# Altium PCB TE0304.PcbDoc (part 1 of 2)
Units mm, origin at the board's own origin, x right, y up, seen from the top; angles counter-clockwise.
Board outline 115 x 73 mm, 4 copper layers (L 01 (Top), L 02, L 03, L 04 (Bot)), stack 1.564 mm thick; 95 components, 174 nets, 553 pads, 126 vias.
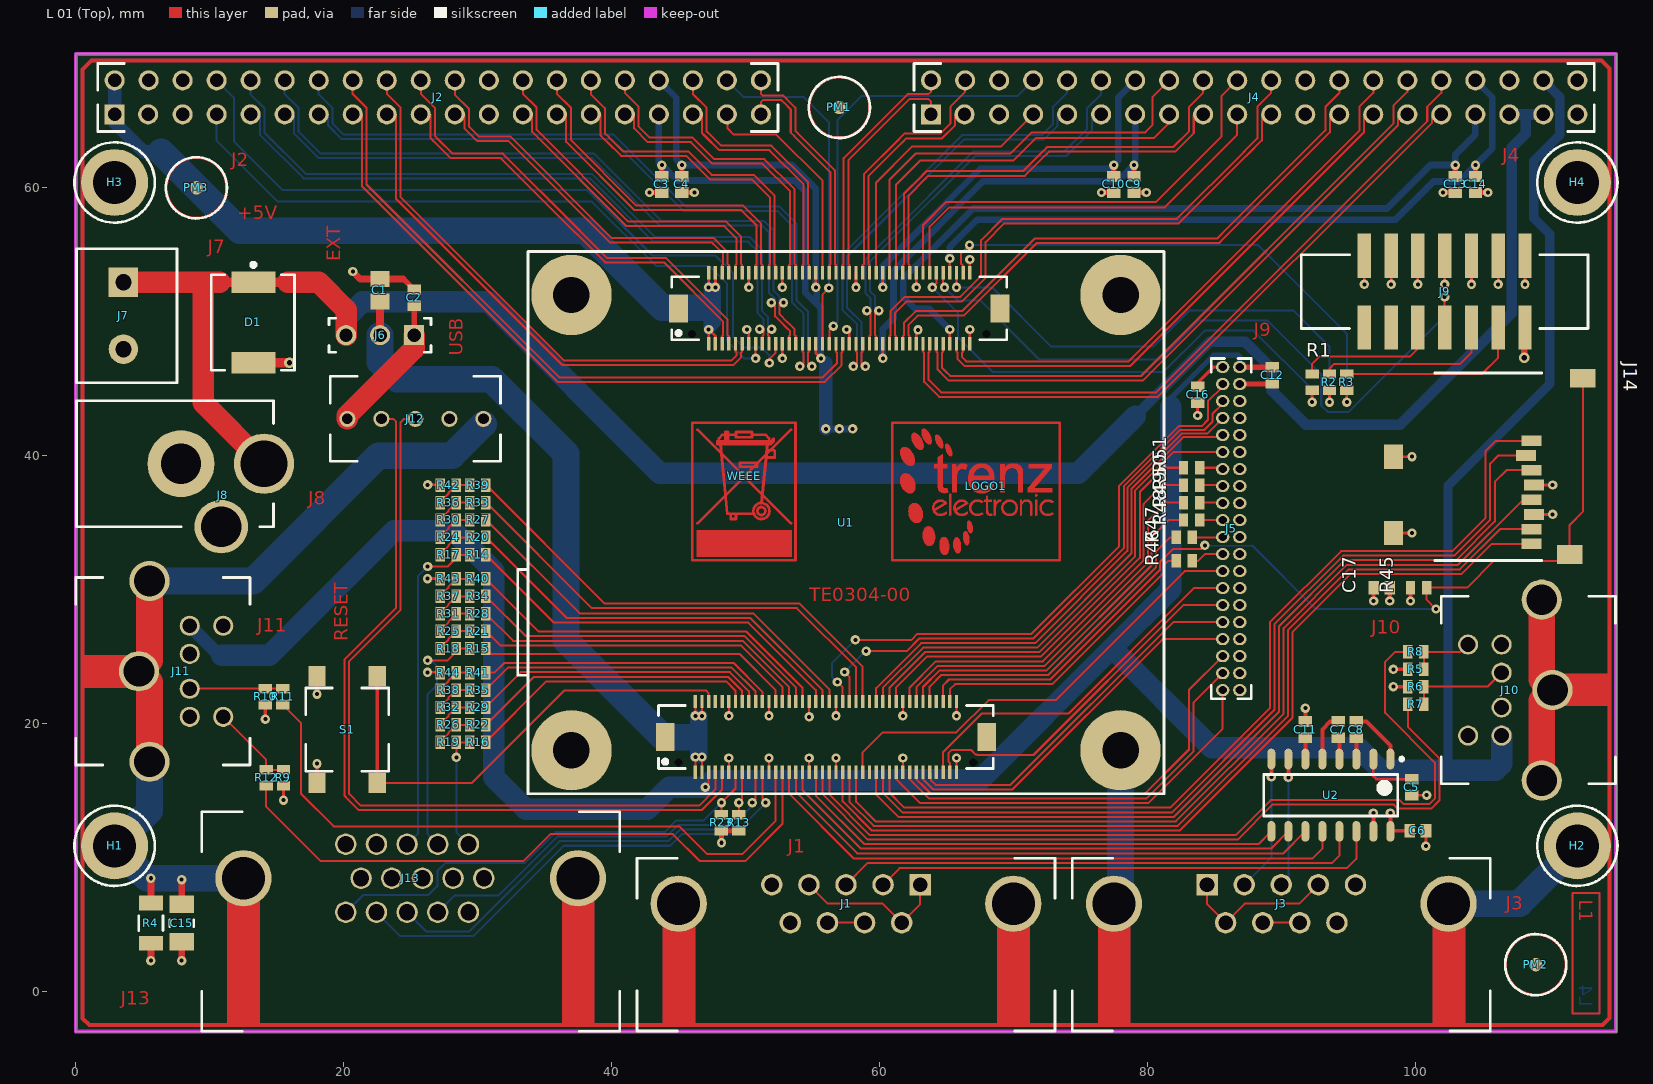
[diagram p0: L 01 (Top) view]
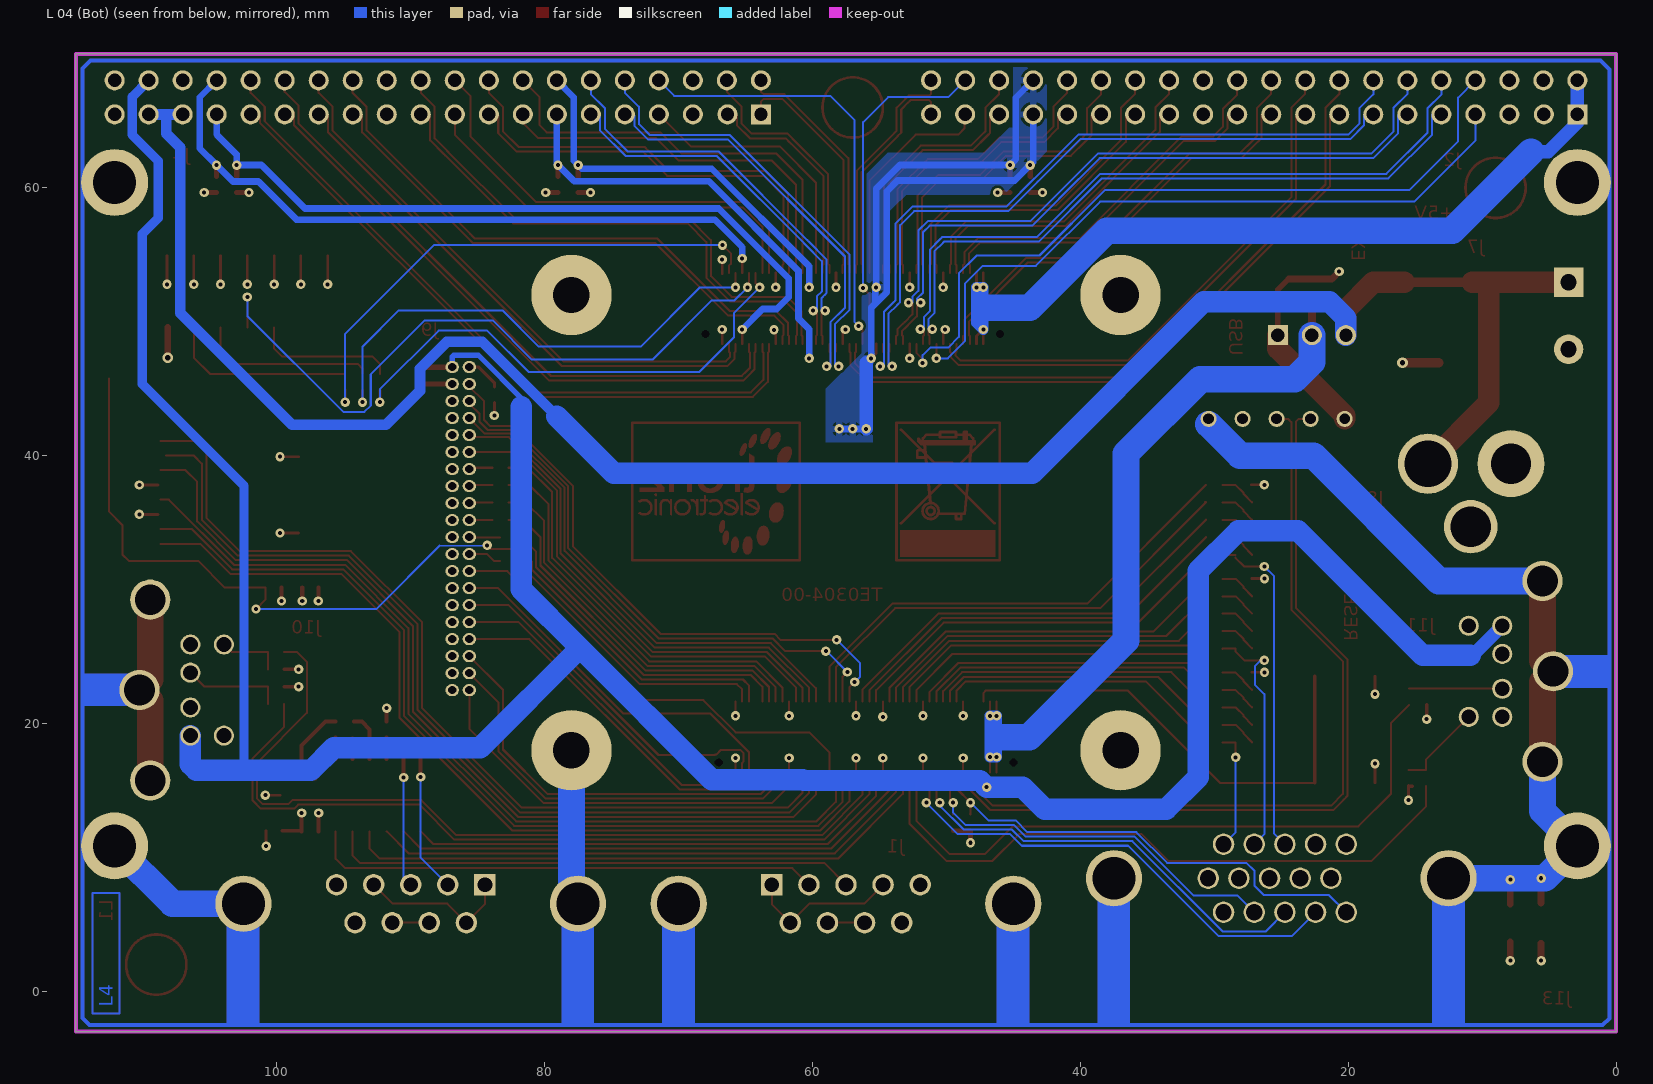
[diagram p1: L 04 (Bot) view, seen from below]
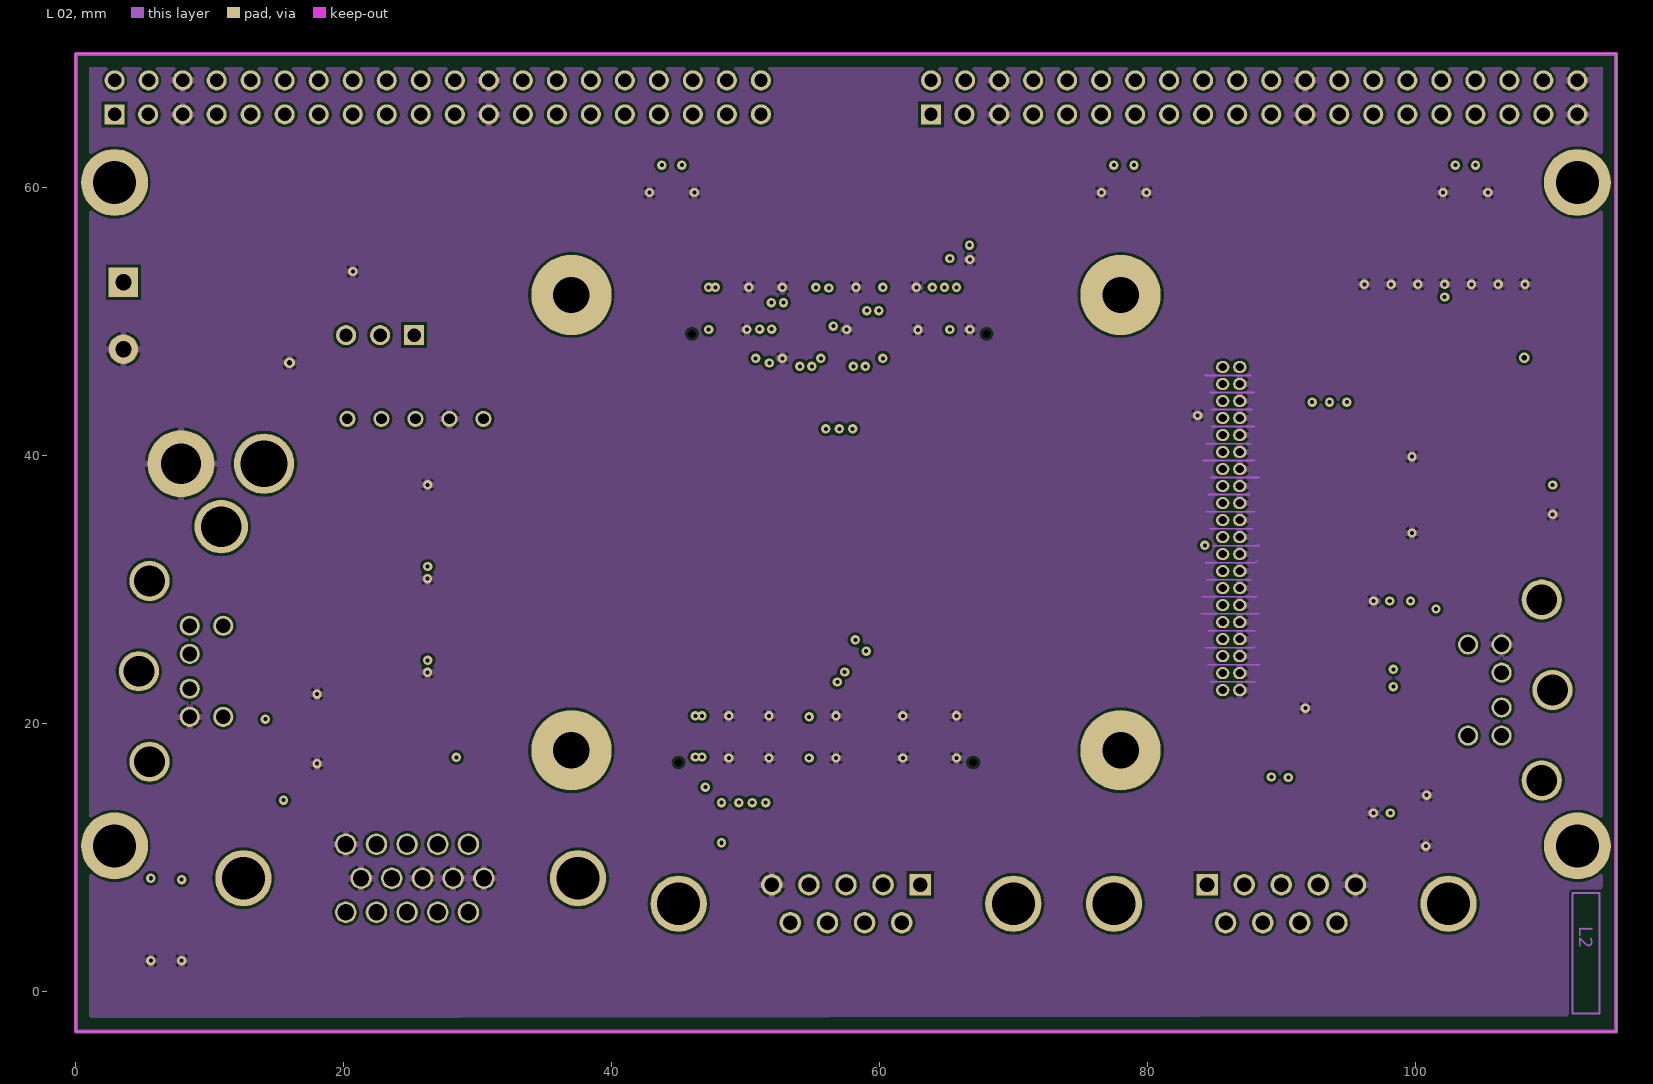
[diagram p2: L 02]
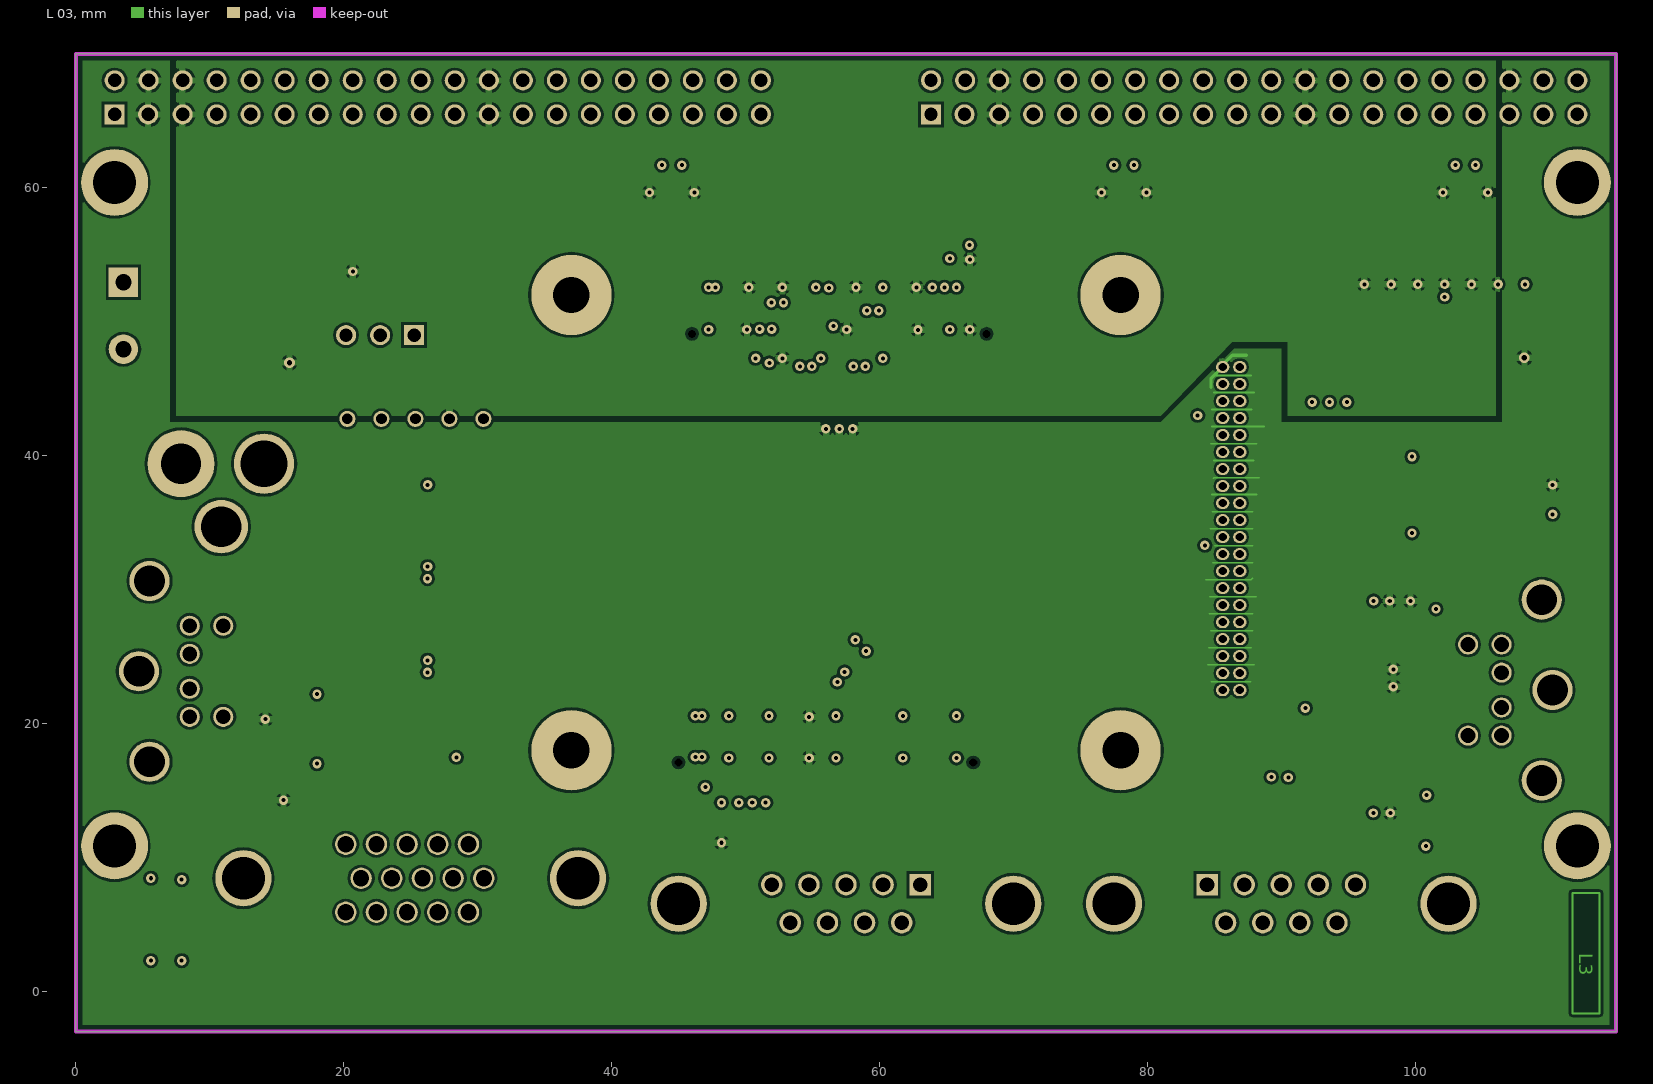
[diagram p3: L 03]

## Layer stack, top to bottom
L 01 (Top): signal copper 0.05
Dielectric: core 0.134, FR-4, Dk 4.8
L 02: signal copper 0.033
Dielectric: prepreg 1.13, FR-4, Dk 4.8
L 03: signal copper 0.033
Dielectric: core 0.134, FR-4, Dk 4.8
L 04 (Bot): signal copper 0.05

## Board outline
0,-3 0,70 115,70 115,-3

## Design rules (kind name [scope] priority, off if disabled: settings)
Clearance Clearance_Polygon [(InPolygon)] p1: gap=0.2
Clearance [All] p2: gap=0.12
ComponentClearance ComponentClearance_WEEE [(InComponent('WEEE'))] p1: gap=-20 collisioncheckmode=3 verticalgap=0.254 showdistances=FALSE
ComponentClearance ComponentClearance_LOGO [(InComponent('LOGO1'))] p2: gap=-80 collisioncheckmode=3 verticalgap=0.254 showdistances=TRUE
ComponentClearance [All] p3: gap=-0.05 collisioncheckmode=3 verticalgap=0.254 showdistances=FALSE
DiffPairsRouting [All] p1: maxlimit=1 minlimit=0.189 mostfreqgap=1 toplayer_maxgap=0.191 toplayer_prefgap=0.19 midlayer1_mingap=1 midlayer2_mingap=1 bottomlayer_maxgap=0.191 bottomlayer_prefgap=0.19 maxuncoupledlength=12.7
FabricationTestPointUsage TestPointUsage [All] p1: valid=0 allowmultiple=FALSE
FabricationTestpoint Testpoint [All] p1: side=3 testpointundercomponent=TRUE minsize=1.016 maxsize=2.54 preferedsize=1.524 minholesize=0 maxholesize=1.016 preferedholesize=0.813 testpointgrid=0.025 allowsidetop=TRUE allowsidebottom=TRUE usegrid=TRUE gridtolerance=0
HoleSize [All] p1: absolutevalues=TRUE maxlimit=5 minlimit=0.3 maxpercent=80.000 minpercent=20.000
MinimumAnnularRing [Not(InComponent('J7'))] p1: minimumring=0.15
PolygonConnect [All] p1: connectstyle=Relief reliefconductorwidth=0.5 reliefentries=4 polygonreliefangle="90 Angle"
RoutingLayers [All] p1: top layer_v5=TRUE mid layer 1_v5=FALSE mid layer 2_v5=FALSE bottom layer_v5=TRUE
RoutingVias [All] p1: holewidth=0.3 width=0.8 viastyle="Through Hole" minholewidth=0.3 minwidth=0.7 maxholewidth=1 maxwidth=3
SMDNeckDown [InSMTComponent] p1: percent=50.000
SilkscreenOverComponentPads [All] p1: minsilkscreentomaskgap=0.254
SolderMaskExpansion SolderMaskExpansion_VIA [(IsVia)] p1: expansion=-10
SolderMaskExpansion [All] p2: expansion=0.102
Width Width_logo [InComponent(LOGO1)] p1: maxlimit=0.254 minlimit=0.004 preferedwidth=0.254
Width Width_100Ohm [(InNetClass('I100'))] p2: maxlimit=0.15 minlimit=0.15 preferedwidth=0.15
Width [All] p3: maxlimit=3 minlimit=0.12 preferedwidth=0.2
21 further rules are at their usual default settings.

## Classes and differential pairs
component class VGA: J13 R13 R14 R15 R16 R17 R18 R19 R20 R21 R22 R23 R24 R25 R26 R27 R28 R29 R30 R31 R32 R33 R34 R35 R36 R37 R38 R39 R40 R41 R42 R43 R44
component class Main: H1 H2 H3 H4 LOGO1 PM1 PM2 PM3 WEEE
component class Signals: C1 C2 C15 D1 J6 J7 J8 J9 J12 R1 R2 R3 R4 S1 U1
component class Connector: C3 C4 C5 C6 C7 C8 C9 C10 C11 C12 C13 C14 C16 C17 J1 J2 J3 J4 J5 J10 J11 J14 R5 R6 R7 R8 R9 R10 R11 R12 R45 R46 R47 R48 R49 R50 R51 U2
net class I100: B0_L01_N B0_L01_P B0_L03_N B0_L03_P B0_L04_N B0_L04_P B0_L05_N B0_L05_P B0_L06_N B0_L06_P B0_L08_N B0_L08_P B0_L09_N B0_L09_P B0_L15_N B0_L15_P B0_L17_N B0_L17_P B0_L18_N B0_L18_P B0_L19_N B0_L19_P B0_L20_N B0_L20_P B0_L21_N B0_L21_P B0_L23_N B0_L23_P B0_L24_N B0_L24_P B3_L01_N B3_L01_P B3_L02_N B3_L02_P B3_L03_N B3_L03_P B3_L07_N B3_L07_P GCLK_L11_N GCLK_L11_P GCLK_L12_N GCLK_L12_P GCLK_L13_N GCLK_L13_P GCLK_L14_N GCLK_L14_P USB_D_N USB_D_P
differential pair USB_D: +USB_D_P -USB_D_N
differential pair B0_L01: +B0_L01_P -B0_L01_N
differential pair B0_L03: +B0_L03_P -B0_L03_N
differential pair B0_L04: +B0_L04_P -B0_L04_N
differential pair B0_L05: +B0_L05_P -B0_L05_N
differential pair B0_L06: +B0_L06_P -B0_L06_N
differential pair B0_L08: +B0_L08_P -B0_L08_N
differential pair B0_L09: +B0_L09_P -B0_L09_N
differential pair B0_L15: +B0_L15_P -B0_L15_N
differential pair B0_L17: +B0_L17_P -B0_L17_N
differential pair B0_L18: +B0_L18_P -B0_L18_N
differential pair B0_L19: +B0_L19_P -B0_L19_N
differential pair B0_L20: +B0_L20_P -B0_L20_N
differential pair B0_L21: +B0_L21_P -B0_L21_N
differential pair B0_L23: +B0_L23_P -B0_L23_N
differential pair B0_L24: +B0_L24_P -B0_L24_N
differential pair B3_L01: +B3_L01_P -B3_L01_N
differential pair B3_L03: +B3_L03_P -B3_L03_N
differential pair B3_L07: +B3_L07_P -B3_L07_N
differential pair GCLK_L11: +GCLK_L11_P -GCLK_L11_N
differential pair GCLK_L12: +GCLK_L12_P -GCLK_L12_N
differential pair GCLK_L13: +GCLK_L13_P -GCLK_L13_N
differential pair GCLK_L14: +GCLK_L14_P -GCLK_L14_N
differential pair B3_L02: +B3_L02_P -B3_L02_N

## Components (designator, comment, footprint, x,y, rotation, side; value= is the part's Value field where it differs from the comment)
C1 "10µF" CAPC2012N 22.7,52.35 r270 top
C2 "100nF" CAPC1608N 25.25,51.8 r90 top
C3 "100nF" CAPC1608N 43.75,60.25 r270 top
C4 "100nF" CAPC1608N 45.25,60.25 r270 top
C5 "100nF" CAPC1608N 99.75,15.25 r270 top
C6 "100nF" CAPC1608N 100.2,12 r0 top
C7 "100nF" CAPC1608N 94.25,19.55 r90 top
C8 "100nF" CAPC1608N 95.6,19.55 r270 top
C9 "100nF" CAPC1608N 79,60.25 r270 top
C10 "100nF" CAPC1608N 77.5,60.25 r270 top
C11 "100nF" CAPC1608N 91.8,19.55 r90 top
C12 "100nF" CAPC1608N 89.315,46.005 r270 top
C13 "100nF" CAPC1608N 103,60.25 r270 top
C14 "100nF" CAPC1608N 104.5,60.25 r270 top
C15 "100pF" CAPC3216N 7.9,5.1 r270 top
C16 "100nF" CAPC1608N 83.75,44.55 r270 top
C17 "100nF" CAPC1608N 97.5,30.15 r180 top
D1 "MBRS340T3" MBRS340T3 13.25,49.95 r90 top
H1 "MHole3.2mm" MHole3_2mm 2.89,10.87 r0 top
H2 "MHole3.2mm" MHole3_2mm 112.11,10.87 r0 top
H3 "MHole3.2mm" MHole3_2mm 2.89,60.4 r0 top locked
H4 "MHole3.2mm" MHole3_2mm 112.11,60.4 r0 top locked
J1 "DSUB9-F-WIESON 3170" "WIESON 3170-9F" 57.5,6.55 r180 top locked
J2 "STIFTLEISTE2.54 OG 2R-40" "STIFTLEISTE2_54 OG 2R-40" 27.02,66.75 r0 top locked
J3 "DSUB9-M-WIESON 3170" "WIESON 3170-9M" 90,6.55 r180 top locked
J4 "STIFTLEISTE2.54 OG 2R-40" "STIFTLEISTE2_54 OG 2R-40" 87.98,66.75 r0 top locked
J5 "712-40-20-60" 712-40-20-60 86.265,34.555 r90 top
J6 "JUMPER2.54-3" JUMPER2_54-3 25.25,49 r0 top
J7 "ARK500-2" ARK500-2 3.55,50.45 r270 top
J8 "2.5MM_BUCHSE" WS-DC001 14.05,39.4 r0 top
J9 "WANNE2mm2R-14" WANNE2mm2R-14 102.2,52.25 r180 top locked
J10 "MINI DIN 6" "MINI DIN 6" 107.1,22.5 r270 top
J11 "MINI DIN 6" "MINI DIN 6" 7.85,23.9 r90 top
J12 "USB PCB Header" 14191 25.35,42.75 r180 top
J13 "DSUB-HD15-FM 8.89" "WIESON 3110 F" 25,8.45 r180 top locked
J14 "Micro SD Socket" 112A-TXAR-R01 105.45,39.2 r270 top locked
LOGO1 "LOGO TOP" "Logo Top" 67.95,37.7 r0 top
PM1 "FIDU-DOT" FIDU-DOT 57,66 r0 top locked
PM2 "FIDU-DOT" FIDU-DOT 109,2 r0 top
PM3 "FIDU-DOT" FIDU-DOT 9,60 r0 top locked
R1 "100R" RESC1609N 92.3,45.5 r90 top
R2 "100R" RESC1609N 93.6,45.5 r90 top
R3 "100R" RESC1609N 94.9,45.5 r90 top
R4 "1M" RESC3216N 5.6,5.1 r270 top
R5 "3K3" RESC1609N 100.05,24.05 r0 top
R6 "3K3" RESC1609N 100.05,22.75 r0 top
R7 "220R" RESC1609N 100.05,21.45 r180 top
R8 "220R" RESC1609N 100.05,25.35 r180 top
R9 "3K3" RESC1609N 15.5,15.95 r90 top
R10 "3K3" RESC1609N 14.15,22 r90 top
R11 "220R" RESC1609N 15.45,22 r270 top
R12 "220R" RESC1609N 14.2,15.95 r270 top
R13 "2K2" RESC1609N 49.5,12.6 r270 top
R14 "360R" RESC1609N 30,32.6 r0 top
R15 "360R" RESC1609N 30,25.6 r0 top
R16 "360R" RESC1609N 30,18.6 r0 top
R17 "180R" RESC1609N 27.8,32.6 r180 top
R18 "180R" RESC1609N 27.8,25.6 r180 top
R19 "180R" RESC1609N 27.8,18.6 r180 top
R20 "360R" RESC1609N 30,33.9 r0 top
R21 "360R" RESC1609N 30,26.9 r0 top
R22 "360R" RESC1609N 30,19.9 r0 top
R23 "2K2" RESC1609N 48.2,12.6 r270 top
R24 "180R" RESC1609N 27.8,33.9 r180 top
R25 "180R" RESC1609N 27.8,26.9 r180 top
R26 "180R" RESC1609N 27.8,19.9 r180 top
R27 "360R" RESC1609N 30,35.2 r0 top
R28 "360R" RESC1609N 30,28.2 r0 top
R29 "360R" RESC1609N 30,21.2 r0 top
R30 "180R" RESC1609N 27.8,35.2 r180 top
R31 "180R" RESC1609N 27.8,28.2 r180 top
R32 "180R" RESC1609N 27.8,21.2 r180 top
R33 "360R" RESC1609N 30,36.5 r0 top
R34 "360R" RESC1609N 30,29.5 r0 top
R35 "360R" RESC1609N 30,22.5 r0 top
R36 "180R" RESC1609N 27.8,36.5 r180 top
R37 "180R" RESC1609N 27.8,29.5 r180 top
R38 "180R" RESC1609N 27.8,22.5 r180 top
R39 "360R" RESC1609N 30,37.8 r0 top
R40 "360R" RESC1609N 30,30.8 r0 top
R41 "360R" RESC1609N 30,23.8 r0 top
R42 "180R" RESC1609N 27.8,37.8 r180 top
R43 "180R" RESC1609N 27.8,30.8 r180 top
R44 "180R" RESC1609N 27.8,23.8 r180 top
R45 "3K3" RESC1609N 100.25,30.15 r180 top
R46 "100R" RESC1609N 82.75,32.15 r180 top
R47 "100R" RESC1609N 82.75,33.9 r180 top
R48 "100R" RESC1609N 83.3,35.2 r180 top
R49 "100R" RESC1609N 83.3,36.5 r180 top
R50 "100R" RESC1609N 83.3,37.8 r180 top
R51 "0R" RESC1609N 83.3,39.1 r180 top
S1 "SW PB DTSM61N" DTSM61N 20.25,19.55 r270 top
U1 "TE0300-01" TE0300-01 57.5,35 r90 top locked
U2 "ICL3232IBNZ" SOIC127P600X175-16N 93.7,14.65 r270 top
WEEE "WEEE TOP" WEEETOP_10_25mm 49.9,38.45 r0 top

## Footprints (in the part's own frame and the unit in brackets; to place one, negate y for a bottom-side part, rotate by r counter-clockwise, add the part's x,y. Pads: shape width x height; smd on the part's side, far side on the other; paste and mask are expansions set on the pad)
112A-TXAR-R01 [mm] "Micro SD Socket"
  rect 0.8x1.5 smd: 1(-1.915,3.225) 2(-0.815,2.825) 3(0.285,3.225) 4(1.385,3.425) 5(2.485,3.225) 6(3.585,3.425) 7(4.685,3.225) 8(5.785,3.225)
  rect 1.4x1.9 smd: 9(-6.575,7.075) 9(6.575,6.075)
  rect 1.8x1.4 smd: 10(-0.725,-7.075) 10(4.975,-7.075)
  silkscreen extent -6.97,-4 7.03,4, body extent -8.02,-8.77 8.02,13, height 1.83
712-40-20-60 [mm]
  oval 0.9x1 hole 0.6: 1(-12.065,-0.635) 2(-12.065,0.635) 3(-10.795,-0.635) 4(-10.795,0.635) 5(-9.525,-0.635) 6(-9.525,0.635) 7(-8.255,-0.635) 8(-8.255,0.635) 9(-6.985,-0.635) 10(-6.985,0.635) 11(-5.715,-0.635) 12(-5.715,0.635) 13(-4.445,-0.635) 14(-4.445,0.635) 15(-3.175,-0.635) 16(-3.175,0.635) 17(-1.905,-0.635) 18(-1.905,0.635) 19(-0.635,-0.635) 20(-0.635,0.635) 21(0.635,-0.635) 22(0.635,0.635) 23(1.905,-0.635) 24(1.905,0.635) 25(3.175,-0.635) 26(3.175,0.635) 27(4.445,-0.635) 28(4.445,0.635) 29(5.715,-0.635) 30(5.715,0.635) 31(6.985,-0.635) 32(6.985,0.635) 33(8.255,-0.635) 34(8.255,0.635) 35(9.525,-0.635) 36(9.525,0.635) 37(10.795,-0.635) 38(10.795,0.635) 39(12.065,-0.635) 40(12.065,0.635)
  silkscreen extent -12.7,-1.5 12.7,1.5, body extent -12.95,-1.75 12.95,1.75, height 5.5
14191 [mm] "PCB Adaptor Leads"
  round 1.2 hole 0.8: 1(5.08,0) 2(2.54,0) 3(0,0) 4(-2.54,0) 5(-5.08,0)
  silkscreen extent -6.35,-3.18 6.35,3.18, body extent -6.6,-3.42 6.6,3.42, height 12
ARK500-2 [mm] "AR-Klemmen 250V 2pol. grau"
  rect 2.2x2.2 hole 1.2: 1(-2.5,0)
  round 2.2 hole 1.2: 2(2.5,0)
  silkscreen extent -5,-3.5 5,4, body extent -6.6,-4.5 6,5, height 10
CAPC1608N [mm] "Vishay VJ0603 1.6 x 0.8 (+0.15/-0.1) 0.4 +/- 0,15mm Kontakte"
  rect 0.8x1 smd: 1(-0.6,0) 2(0.6,0)
  body extent -1.15,-0.65 1.15,0.65, height 0.95
CAPC2012N [mm] "Vishay VJ0805 2 x 1.25 +/- 0.15, 0.5 +/- 0,2 Kontakte"
  rect 1.2x1.4 smd: 1(-0.85,0) 2(0.85,0)
  body extent -1.7,-0.95 1.7,0.95, height 1.35
CAPC3216N [mm] "Vishay VJ1206 3.2 x 1.6 (+/- 0.15), 0.4mm - 0.8mm Kontakte"
  rect 1.3x1.8 smd: 1(-1.4,0) 2(1.4,0)
  silkscreen extent -0.25,-0.9 0.25,0.9, body extent -2.3,-1.15 2.3,1.15, height 1.8
DTSM61N [mm] "SMD-Taster"
  rect 1.55x1.3 smd: 1(-3.975,2.25) 1(3.975,2.25) 2(-3.975,-2.25) 2(3.975,-2.25)
  silkscreen extent -3.1,-3.1 3.1,3.1, body extent -5,-4.1 5,4.1, height 4.5
FIDU-DOT [mm]
  round 1 smd paste-1 mask+2: 0(0,0)
  L 01 (Top) circle w0.2: c0,0 r2.25
  silkscreen extent -2.28,-2.29 2.29,2.29
JUMPER2_54-3 [mm]
  rect 1.5x1.5 hole 1: 1(0,0)
  round 1.5 hole 1: 2(-2.54,0) 3(-5.08,0)
  silkscreen extent -6.35,-1.27 1.27,1.27, body extent -3.54,-1 -1.54,1, height 8
"Logo Top" [mm]
  L 01 (Top) drawing of 1838 lines, arcs and shapes, not listed
MBRS340T3 [mm]
  rect 1.6x3.27 smd: 1(3,0) 2(-3,0)
  silkscreen extent -3.56,-3.07 4.45,3.15, body extent -4.56,-4.07 4.55,4.15, height 2.6
MHole3_2mm [mm]
  round 5 hole 3.2: 1(0,0)
  silkscreen extent -3,-3 3,3
"MINI DIN 6" [mm]
  round 1.5 hole 1.1: 1(-1.3,-0.65) 2(1.3,-0.65) 3(-3.4,-0.65) 4(3.4,-0.65) 5(-3.4,-3.15) 6(3.4,-3.15)
  round 3 hole 2.3: S1(6.75,2.35) S2(0,3.15) S3(-6.75,2.35)
  silkscreen extent -7,-5.15 7,7.85, body extent -8.5,-5.4 8.5,8.1, height 13.4
RESC1609N [mm] "Vishay D0603 1.55 x 0.85 (+0.1/-0.05) 0.3 +/- 0,2mm Kontakte"
  rect 0.7x1 smd: 1(-0.6,0) 2(0.6,0)
  body extent -1.1,-0.65 1.1,0.65, height 0.5
RESC3216N [mm] "Vishay D1206 3.2 x 1.6 (+/- 0.15), 0.2mm - 0.6mm Kontakte"
  rect 1.1x1.8 smd: 1(-1.5,0) 2(1.5,0)
  silkscreen extent -0.55,-0.9 0.55,0.9, body extent -2.3,-1.15 2.3,1.15, height 0.6
SOIC127P600X175-16N [mm] "SOIC, 16-Leads, Body 10,0x4,0mm (max), Pitch 1,27mm, IPC Medium Density"
  oval 1.55x0.6 smd: 1(-2.7,4.445) 2(-2.7,3.175) 3(-2.7,1.905) 4(-2.7,0.635) 5(-2.7,-0.635) 6(-2.7,-1.905) 7(-2.7,-3.175) 8(-2.7,-4.445) 9(2.7,-4.445) 10(2.7,-3.175) 11(2.7,-1.905) 12(2.7,-0.635) 13(2.7,0.635) 14(2.7,1.905) 15(2.7,3.175) 16(2.7,4.445)
  silkscreen extent -2.82,-5 1.55,5.42, body extent -3.75,-5.25 3.75,5.25, height 1.75
"STIFTLEISTE2_54 OG 2R-40" [mm]
  rect 1.5x1.5 hole 1: 1(-24.13,-1.27)
  round 1.5 hole 1: 2(-24.13,1.27) 3(-21.63,-1.27) 4(-21.59,1.27) 5(-19.05,-1.27) 6(-19.05,1.27) 7(-16.51,-1.27) 8(-16.51,1.27) 9(-13.97,-1.27) 10(-13.97,1.27) 11(-11.43,-1.27) 12(-11.43,1.27) 13(-8.89,-1.27) 14(-8.89,1.27) 15(-6.35,-1.27) 16(-6.35,1.27) 17(-3.81,-1.27) 18(-3.81,1.27) 19(-1.27,-1.27) 20(-1.27,1.27) 21(1.27,-1.27) 22(1.27,1.27) 23(3.81,-1.27) 24(3.81,1.27) 25(6.35,-1.27) 26(6.35,1.27) 27(8.89,-1.27) 28(8.89,1.27) 29(11.43,-1.27) 30(11.43,1.27) 31(13.97,-1.27) 32(13.97,1.27) 33(16.51,-1.27) 34(16.51,1.27) 35(19.05,-1.27) 36(19.05,1.27) 37(21.59,-1.27) 38(21.59,1.27) 39(24.13,-1.27) 40(24.13,1.27)
  silkscreen extent -25.4,-2.54 25.4,2.54, body extent -25.65,-2.79 25.65,2.79, height 11.3
TE0300-01 [mm] "USB-Modul"
  round 6 hole 2.72: 1(-17,20.5) 2(-17,-20.5) 3(17,20.5) 4(17,-20.5)
  round 0 hole 0.6 unplated: A(-17.9,12.5) A(14.1,11.5) B(-17.9,-9.5) B(14.1,-10.5)
  rect 2.1x1.4 smd: G1(-16,13.5) G1(16,12.5) G2(-16,-10.5) G2(16,-11.5)
  rect 1x0.25 smd: J4-1(13.35,10.25) J4-2(18.65,10.25) J4-3(13.35,9.75) J4-4(18.65,9.75) J4-5(13.35,9.25) J4-6(18.65,9.25) J4-7(13.35,8.75) J4-8(18.65,8.75) J4-9(13.35,8.25) J4-10(18.65,8.25) J4-11(13.35,7.75) J4-12(18.65,7.75) J4-13(13.35,7.25) J4-14(18.65,7.25) J4-15(13.35,6.75) J4-16(18.65,6.75) J4-17(13.35,6.25) J4-18(18.65,6.25) J4-19(13.35,5.75) J4-20(18.65,5.75) J4-21(13.35,5.25) J4-22(18.65,5.25) J4-23(13.35,4.75) J4-24(18.65,4.75) J4-25(13.35,4.25) J4-26(18.65,4.25) J4-27(13.35,3.75) J4-28(18.65,3.75) J4-29(13.35,3.25) J4-30(18.65,3.25) J4-31(13.35,2.75) J4-32(18.65,2.75) J4-33(13.35,2.25) J4-34(18.65,2.25) J4-35(13.35,1.75) J4-36(18.65,1.75) J4-37(13.35,1.25) J4-38(18.65,1.25) J4-39(13.35,0.75) J4-40(18.65,0.75) J4-41(13.35,0.25) J4-42(18.65,0.25) J4-43(13.35,-0.25) J4-44(18.65,-0.25) J4-45(13.35,-0.75) J4-46(18.65,-0.75) J4-47(13.35,-1.25) J4-48(18.65,-1.25) J4-49(13.35,-1.75) J4-50(18.65,-1.75) J4-51(13.35,-2.25) J4-52(18.65,-2.25) J4-53(13.35,-2.75) J4-54(18.65,-2.75) J4-55(13.35,-3.25) J4-56(18.65,-3.25) J4-57(13.35,-3.75) J4-58(18.65,-3.75) J4-59(13.35,-4.25) J4-60(18.65,-4.25) J4-61(13.35,-4.75) J4-62(18.65,-4.75) J4-63(13.35,-5.25) J4-64(18.65,-5.25) J4-65(13.35,-5.75) J4-66(18.65,-5.75) J4-67(13.35,-6.25) J4-68(18.65,-6.25) J4-69(13.35,-6.75) J4-70(18.65,-6.75) J4-71(13.35,-7.25) J4-72(18.65,-7.25) J4-73(13.35,-7.75) J4-74(18.65,-7.75) J4-75(13.35,-8.25) J4-76(18.65,-8.25) J4-77(13.35,-8.75) J4-78(18.65,-8.75) J4-79(13.35,-9.25) J4-80(18.65,-9.25) J5-1(-18.65,11.25) J5-2(-13.35,11.25) J5-3(-18.65,10.75) J5-4(-13.35,10.75) J5-5(-18.65,10.25) J5-6(-13.35,10.25) J5-7(-18.65,9.75) J5-8(-13.35,9.75) J5-9(-18.65,9.25) J5-10(-13.35,9.25) J5-11(-18.65,8.75) J5-12(-13.35,8.75) J5-13(-18.65,8.25) J5-14(-13.35,8.25) J5-15(-18.65,7.75) J5-16(-13.35,7.75) J5-17(-18.65,7.25) J5-18(-13.35,7.25) J5-19(-18.65,6.75) J5-20(-13.35,6.75) J5-21(-18.65,6.25) J5-22(-13.35,6.25) J5-23(-18.65,5.75) J5-24(-13.35,5.75) J5-25(-18.65,5.25) J5-26(-13.35,5.25) J5-27(-18.65,4.75) J5-28(-13.35,4.75) J5-29(-18.65,4.25) J5-30(-13.35,4.25) J5-31(-18.65,3.75) J5-32(-13.35,3.75) J5-33(-18.65,3.25) J5-34(-13.35,3.25) J5-35(-18.65,2.75) J5-36(-13.35,2.75) J5-37(-18.65,2.25) J5-38(-13.35,2.25) J5-39(-18.65,1.75) J5-40(-13.35,1.75) J5-41(-18.65,1.25) J5-42(-13.35,1.25) J5-43(-18.65,0.75) J5-44(-13.35,0.75) J5-45(-18.65,0.25) J5-46(-13.35,0.25) J5-47(-18.65,-0.25) J5-48(-13.35,-0.25) J5-49(-18.65,-0.75) J5-50(-13.35,-0.75) J5-51(-18.65,-1.25) J5-52(-13.35,-1.25) J5-53(-18.65,-1.75) J5-54(-13.35,-1.75) J5-55(-18.65,-2.25) J5-56(-13.35,-2.25) J5-57(-18.65,-2.75) J5-58(-13.35,-2.75) J5-59(-18.65,-3.25) J5-60(-13.35,-3.25) J5-61(-18.65,-3.75) J5-62(-13.35,-3.75) J5-63(-18.65,-4.25) J5-64(-13.35,-4.25) J5-65(-18.65,-4.75) J5-66(-13.35,-4.75) J5-67(-18.65,-5.25) J5-68(-13.35,-5.25) J5-69(-18.65,-5.75) J5-70(-13.35,-5.75) J5-71(-18.65,-6.25) J5-72(-13.35,-6.25) J5-73(-18.65,-6.75) J5-74(-13.35,-6.75) J5-75(-18.65,-7.25) J5-76(-13.35,-7.25) J5-77(-18.65,-7.75) J5-78(-13.35,-7.75) J5-79(-18.65,-8.25) J5-80(-13.35,-8.25)
  silkscreen extent -20.25,-23.75 20.25,24.51, body extent -2.5,-2.5 2.5,2.5, height 11
WANNE2mm2R-14 [mm]
  rect 1x3.3 smd: 1(-6,-2.685) 2(-6,2.685) 3(-4,-2.685) 4(-4,2.685) 5(-2,-2.685) 6(-2,2.685) 7(0,-2.685) 8(0,2.685) 9(2,-2.685) 10(2,2.685) 11(4,-2.685) 12(4,2.685) 13(6,-2.685) 14(6,2.685)
  silkscreen extent -10.7,-2.75 10.7,2.75, body extent -11.6,-4.6 11.6,4.6, height 6.5
WEEETOP_10_25mm [mm]
  L 01 (Top) circle w0.2: c1.283,-2.583 r0.3
  L 01 (Top) circle w0.2: c1.283,-2.583 r0.6
  L 01 (Top) region: -3.574,-6.001 3.551,-6.001 3.551,-4.001 -3.574,-4.001
  L 01 (Top) lines w0.2: -3.499,-3.501 3.501,3.499 ; -3.499,3.499 3.501,-3.501 ; -1.892,2.617 -1.892,2.842 -1.617,3.117 -0.617,3.117 ; -1.767,2.417 -1.267,-2.783 0.733,-2.783 ; -1.617,2.417 1.983,2.417 ; -1.417,2.617 -1.417,3.317 -1.217,3.317 -1.217,2.617 ; -1.017,-2.783 -1.017,-3.183 -0.617,-3.183 -0.617,-2.783 ; 0.583,3.117 0.783,3.117 1.583,3.117 1.858,2.842 1.858,2.617 ; 1.293,-1.983 1.733,2.417 ; 1.647,1.415 2.281,1.415 2.283,1.417 2.283,1.917 2.252,1.948 1.686,1.948 ; 1.983,2.417 -2.017,2.417 -2.017,2.617 1.983,2.617 2.183,2.817 2.183,2.617 1.983,2.417 ; -3.874,-6.251 -3.874,3.999 3.826,3.999 3.826,-6.251 -3.874,-6.251 ; -0.617,2.917 -0.617,3.317 0.583,3.317 0.583,2.917 -0.617,2.917 ; -0.317,0.717 -0.317,1.017 0.983,1.017 0.983,0.717 -0.317,0.717
"WIESON 3110 F" [mm]
  round 1.6 hole 1.2: 1(-4.31,-2.54) 2(-2.02,-2.54) 3(0.27,-2.54) 4(2.56,-2.54) 5(4.85,-2.54) 6(-5.455,0) 7(-3.165,0) 8(-0.875,0) 9(1.415,0) 10(3.705,0) 11(-4.31,2.54) 12(-2.02,2.54) 13(0.27,2.54) 14(2.56,2.54) 15(4.85,2.54)
  round 4.2 hole 3.2: S1(-12.495,0) S2(12.495,0)
  silkscreen extent -15.6,-4.97 15.6,11.43, body extent -15.85,-5.22 15.85,11.43, height 12.9
"WIESON 3170-9F" [mm]
  rect 1.6x1.6 hole 1.1: 1(-5.54,-1.42)
  round 1.6 hole 1.1: 2(-2.77,-1.42) 3(0,-1.42) 4(2.77,-1.42) 5(5.54,-1.42) 6(-4.155,1.42) 7(-1.385,1.42) 8(1.385,1.42) 9(4.155,1.42)
  round 4.2 hole 3.2: S1(-12.495,0) S2(12.495,0)
  silkscreen extent -15.6,-3.4 15.6,9.5, body extent -15.85,-3.65 15.85,9.5, height 12.8
"WIESON 3170-9M" [mm]
  rect 1.6x1.6 hole 1.1: 1(5.54,-1.42)
  round 1.6 hole 1.1: 2(2.77,-1.42) 3(0,-1.42) 4(-2.77,-1.42) 5(-5.54,-1.42) 6(4.155,1.42) 7(1.385,1.42) 8(-1.385,1.42) 9(-4.155,1.42)
  round 4.2 hole 3.2: S1(-12.495,0) S2(12.495,0)
  silkscreen extent -15.6,-3.4 15.6,9.5, body extent -15.85,-3.65 15.85,9.5, height 12.8
WS-DC001 [mm]
  round 4.5 hole 3.5: 1(0,0)
  round 4 hole 3: 2(-3.2,-4.7)
  round 5 hole 3: 3(-6.2,0)
  silkscreen extent -14,-4.7 0.7,4.7, body extent -14.25,-6.95 2.5,5, height 11.3

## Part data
C1: library part 22478
C2 C3 C4 C5 C6 C7 C8 C9 C10 C11 C12 C13 C14 C16 C17: library part 21382
C15: library part 22679
D1: library part 22887
H1 H2 H3 H4: library part 22898
J1: library part 22388, "DSUB 9 Female US Kurz 90° Einlöt"
J2 J4: library part 22320
J3: library part 22390, "DSUB 9 Male US Kurz 90° Einlöt"
J5: library part 23184
J6: library part 22328, "Jumper"
J7: library part 20123
J8: library part 22398, "2.5mm Stromversorgungsbuchse"
J9: library part 22744
J10 J11: library part 22383, "PS/2"
J12: library part 23194
J13: library part 21395
J14: library part 23193
LOGO1: library part 22901
PM1 PM2 PM3: library part 22906
R1 R46 R47 R48 R49 R50 R51: library part 21380
R2 R3: library part 22507
R4: library part 22757
R5 R6 R9 R10 R45: library part 22433
R7 R8 R11 R12: library part 22324
R13 R23: library part 21377
R14 R15 R16 R20 R21 R22 R27 R28 R29 R33 R34 R35 R39 R40 R41: library part 22862
R17 R18 R19 R24 R25 R26 R30 R31 R32 R36 R37 R38 R42 R43 R44: library part 22860
S1: library part 22596
U2: library part 22710, "3.3VV RS232 Dual Driver / Receiver 0,1µF"
WEEE: library part 22300

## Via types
v1: diameter 0.7, hole 0.3, L 01 (Top) to L 04 (Bot), 124 vias
v2: diameter 0.8, hole 0.4, L 01 (Top) to L 04 (Bot), 2 vias

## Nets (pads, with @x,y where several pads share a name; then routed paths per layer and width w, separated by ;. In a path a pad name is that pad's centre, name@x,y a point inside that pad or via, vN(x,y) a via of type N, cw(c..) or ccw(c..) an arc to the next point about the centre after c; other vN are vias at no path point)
1V2_1: U1.J5-73
1V2_2: U1.J5-74
1V2_3: C13.1 J4.33 U1.J4-73 | length 56.9
  L 01 (Top) w0.2: U1.J4-73@65.25,48.35 v1(65.25,49.425)
  L 01 (Top) w0.4: C13.1@103,60.85 v1(103,61.7)
  L 04 (Bot) w0.5: v1(65.25,49.425) 63.725,50.95 62.675,50.95 61.775,51.85 61.775,53.225 67,58.45 97.9,58.45 101.15,61.7 v1(103,61.7) 103,62.5 104.49,63.99 J4.33@104.49,65.48
1V2_4: C14.1 J4.34 U1.J4-74 | length 51.9
  L 01 (Top) w0.2: U1.J4-74@65.25,53.65 v1(65.25,54.725)
  L 01 (Top) w0.4: C14.1@104.5,60.85 v1(104.5,61.7)
  L 04 (Bot) w0.5: v1(65.25,54.725) 65.25,55.575 67.3,57.625 98.525,57.625 101.375,60.475 103.275,60.475 v1(104.5,61.7) 105.75,62.95 105.75,66.76 J4.34@104.49,68.02
2V5_1: U1.J5-53
2V5_2: U1.J5-54
2V5_3: C9.1 J4.13 U1.J4-53 | length 33.8
  L 01 (Top) w0.2: v1(60.25,47.275) U1.J4-53@60.25,48.35
  L 01 (Top) w0.4: C9.1@79,60.85 v1(79,61.7)
  L 04 (Bot) w0.5: v1(60.25,47.275) 60.25,49.45 61.05,50.25 61.05,53.8 67.75,60.5 77.8,60.5 v1(79,61.7) 79.09,61.79 J4.13@79.09,65.48
2V5_4: C10.1 J4.14 U1.J4-54 | length 30.9
  L 01 (Top) w0.2: v1(60.25,52.575) U1.J4-54@60.25,53.65
  L 01 (Top) w0.4: C10.1@77.5,60.85 v1(77.5,61.7)
  L 04 (Bot) w0.5: v1(60.25,52.575) 60.25,54.15 67.525,61.425 77.225,61.425 v1(77.5,61.7) 77.825,62.025 77.825,66.755 J4.14@79.09,68.02
3.3V: C3.1 C4.1 C6.1 C16.1 C17.1 J2.3 J2.4 J2.33 J2.34 J4.36 J5.40 J9.2 J14.4 R5.1 R6.1 R9.1 R10.1 R13.2 R23.2 R45.2 U1.J4-33 U1.J4-34 U1.J5-35 U1.J5-36 U2.16 | length 151.2
  L 01 (Top) w0.15: U1.J5-35@54.75,16.35 v1(54.75,17.425) ; v1(54.75,20.5) U1.J5-36@54.75,21.65
  L 01 (Top) w0.2: U1.J4-33@55.25,48.35 55.25,47.65 v1(55.625,47.275) ; v1(55.25,52.575) U1.J4-34@55.25,53.65 ; J14.4@108.875,37.815 v1(110.265,37.815)
  L 01 (Top) w0.25: v1(14.15,20.325) R10.1@14.15,21.4 ; R9.1@15.2,15.325 R9.1@15.5,15.325 ; v1(15.5,14.275) R9.1@15.5,15.325 ; R9.1@15.5,15.35 R9.1@15.5,15.325 ; R23.2@48.2,11.987 R23.2@48.2,12 ; C16.1@83.75,45.15 83.75,45.45 84.92,46.62 J5.40@85.63,46.62 ; U2.16@98.145,11.95 98.195,12 C6.1@99.6,12 ; v1(98.375,22.75) R6.1@99.45,22.75 ; v1(98.375,24.05) R5.1@99.45,24.05
  L 01 (Top) w0.3: v1(98.1,29.15) C17.1@98.1,30.15 ; U2.16@98.145,11.95 v1(98.145,13.325) ; v1(99.65,29.15) R45.2@99.65,30.15
  L 01 (Top) w0.35: v1(48.2,11.1) R23.2@48.2,12 R13.2@49.5,12
  L 01 (Top) w0.4: C3.1@43.75,60.85 v1(43.75,61.7) ; C4.1@45.25,60.85 v1(45.25,61.7)
  L 01 (Top) w0.5: v2(108.15,47.31) 108.15,49.565 J9.2@108.15,49.6
  L 03 w0.12: 84.35,30.75 87.75,30.75 87.85,30.85 ; 84.515,24.4 87.965,24.4 ; 84.6,25.67 87.75,25.67 ; 84.625,28.21 87.85,28.21 ; 84.65,29.48 88.13,29.48 ; 84.7,34.55 87.85,34.55 ; 84.75,26.93 87.85,26.93 ; 84.75,40.9 88.15,40.9 ; 84.77,23.12 87.7,23.12 ; 84.8,37.1 88.15,37.1 ; 84.8,42.2 84.82,42.18 88.73,42.18 ; 84.8,43.45 87.8,43.45 ; 84.85,35.82 87.85,35.82 ; 84.9,32.02 87.85,32.02 ; 84.932,38.302 84.99,38.36 88.36,38.36 ; 84.95,39.64 87.955,39.64 ; 84.95,44.72 87.985,44.72 ; 84.975,45.965 85,45.99 87.74,45.99 ; 85.05,33.29 87.85,33.29
  L 03 w0.25: 84.75,45.1 84.75,45.74 84.975,45.965 ; 85,45.99 J5.40@85.63,46.62 85.63,46.78 86.355,47.505 87.4,47.505
  L 04 (Bot) w0.5: J2.33@43.53,65.48 43.53,61.92 v1(43.75,61.7) 44.9,60.55 53.649,60.55 54.45,59.749 54.45,52.2 55.325,51.325 ; J2.34@43.53,68.02 44.825,66.725 44.825,62.125 v1(45.25,61.7) 53.475,61.7 55.25,59.925 v1(55.25,52.575) 55.325,52.5 55.325,51.325 ; v1(56,42) v1(57,42) v1(58,42) ; 56,46.95 55.65,47.3 55.625,47.325 55.625,51.025 55.325,51.325
  L 04 (Bot) w1: v1(56,42) 56,46.95
5V: C12.1 J4.38 J5.39 J10.4 J11.4 U1.J5-5 | length 218.5
  L 01 (Top) w0.15: v1(47,15.25) 47.25,15.5 U1.J5-5@47.25,16.35
  L 01 (Top) w0.4: J5.39@86.915,46.605 C12.1@89.315,46.605
  L 01 (Top) w0.5: J5.39@86.9,46.62 J5.39@86.915,46.605
  L 04 (Bot) w0.4: 81.55,44.1 84.96,47.51 86.79,47.51 86.9,47.4 J5.39@86.9,46.62
  L 04 (Bot) w0.7: 102.45,16.5 102.45,37.75 110.05,45.35 110.05,56.55 108.85,57.75 108.85,62 110.8,63.95 110.8,66.79 J4.38@109.57,68.02
  L 04 (Bot) w1: J11.4@8.86,26.94 10.7,25.1 10.9,25.1
  L 04 (Bot) w1.6: 10.9,25.1 14.45,25.1 23.75,34.4 28.2,34.4 31.2,31.4 31.2,16 33.6,13.6 42.65,13.6 44.3,15.25 v1(47,15.25) 47.5,15.75 60.675,15.75 60.735,15.81 67.534,15.81 77.368,25.644 ; 81.75,43.65 81.75,30.026 77.368,25.644 ; J10.4@106.45,19.1 106.45,16.95 106,16.5 102.45,16.5 97.45,16.5 95.75,18.2 84.812,18.2 77.368,25.644
+VB2B: C1.2 J6.2 U1.J5-1 U1.J5-2 U1.J5-3 U1.J5-4 | length 59.3
  L 01 (Top) w0.15: U1.J5-1@46.25,16.35 v1(46.25,17.5) v1@46.25,17.533 ; v1(46.25,20.575) U1.J5-2@46.25,21.65 ; U1.J5-3@46.75,16.35 v1(46.75,17.5) v1@46.75,17.525 ; v1(46.75,20.575) U1.J5-4@46.75,21.65
  L 01 (Top) w0.6: J6.2@22.71,49 C1.2@22.71,51.49
  L 04 (Bot) w0.8: v1(46.25,17.5) v1(46.25,20.575) v1@46.71,20.575 ; v1(46.25,17.5) v1(46.75,17.5) v1(46.75,20.575)
  L 04 (Bot) w2: J6.2@22.71,49 22.71,46.99 24,45.7 31.05,45.7 36.6,40.15 36.6,26.2 43.825,18.975 46.1,18.975
+VCON: D1.1 J4.35 J4.37 J6.3 J7.1 J8.1 | length 161.9
  L 01 (Top) w0.7: 10.75,52.95 D1.1@13.25,52.95 15.802,52.95
  L 01 (Top) w1.6: J7.1@3.55,52.95 9.5,52.95 ; 10.75,52.95 9.5,52.95 ; J8.1@14.05,39.4 9.5,43.95 9.5,52.95 ; 15.802,52.95 18.125,52.95 20.17,50.905 J6.3@20.17,49
  L 04 (Bot) w0.8: 76.15,40 79.096,42.946 84.65,48.5 87.3,48.5 89.315,46.485 89.315,44.84 91.855,42.3 98.85,42.3 107.2,50.65 107.2,63.01 108.25,64.06 108.25,65.48 ; J4.35@107.03,65.48 108.25,65.48 ; J4.37@109.57,65.48 108.25,65.48
  L 04 (Bot) w1.6: J6.3@20.17,49 20.17,50.27 21.4,51.5 30.8,51.5 43.6,38.7 74.85,38.7 79.096,42.946
+VUSB: C2.1 J6.1 J12.1 | length 10.5
  L 01 (Top) w0.4: J6.1@25.25,49 C2.1@25.25,51.2
  L 01 (Top) w1.6: J12.1@20.27,42.75 20.27,43 25.25,47.98 J6.1@25.25,49
/HSYNC: J13.13 U1.J5-19 | length 33
  L 01 (Top) w0.15: v1@50.5,14.289 v1(50.5,14.1) 50.75,14.35 U1.J5-19@50.75,16.35
  L 04 (Bot) w0.15: J13.13@24.73,5.91 26.165,4.475 29.381,4.475 36.122,11.216 44.235,11.216 45.109,12.09 48.721,12.09 50.5,13.869 v1(50.5,14.1)
/MR: S1.1 U1.J5-6 | length 36.3
  L 01 (Top) w0.15: S1.1@22.5,15.575 29.575,15.575 36.47,22.47 47.055,22.47 47.25,22.275 U1.J5-6@47.25,21.65
  L 01 (Top) w0.25: S1.1@22.5,15.575 S1.1@22.5,23.525
/VSYNC: J13.14 U1.J5-21 | length 36.3
  L 01 (Top) w0.15: U1.J5-21@51.25,16.35 51.25,14.35 v1(51.5,14.1)
  L 04 (Bot) w0.15: J13.14@22.44,5.91 24.225,4.125 29.675,4.125 36.426,10.876 44.376,10.876 45.25,11.75 49.15,11.75 v1(51.5,14.1)
B0: R39.2 U1.J5-52 | length 36.4
  L 01 (Top) w0.15: R39.2@30.662,37.825 30.612,37.825 30.618,37.818 39.487,28.95 54.042,28.95 58.75,24.242 U1.J5-52@58.75,21.65
B0_IO_A7: J2.38 U1.J4-35 | length 25.7
  L 01 (Top) w0.15: U1.J4-35@55.75,48.35 55.75,52.05 v1(56.225,52.525)
  L 04 (Bot) w0.15: J2.38@48.61,68.02 49.855,66.775 54.35,66.775 56.225,64.9 v1(56.225,52.525)
B0_IO_A8: J2.37 U1.J4-36 | length 16.6
  L 01 (Top) w0.15: J2.37@48.61,65.48 48.635,65.455 48.635,64.465 49.125,63.975 52.3,63.975 55.75,60.525 U1.J4-36@55.75,53.65
B0_IO_A11: J4.7 U1.J4-52 | length 20.6
  L 01 (Top) w0.15: U1.J4-52@59.75,53.65 59.75,60.4 62.425,63.075 69.065,63.075 J4.7@71.47,65.48
B0_IO_A12: J4.15 U1.J4-58 | length 29.5
  L 01 (Top) w0.15: U1.J4-58@61.25,53.65 61.25,60.25 63.025,62.025 70,62.025 71.7,63.725 80.5,63.725 81.63,64.855 J4.15@81.63,65.48
B0_IO_B11: J4.16 U1.J4-56 | length 32.1
  L 01 (Top) w0.15: U1.J4-56@60.75,53.65 60.75,60.6 62.725,62.575 69.8,62.575 71.375,64.15 79.85,64.15 80.375,64.675 80.375,66.765 J4.16@81.63,68.02
B0_IO_C3: J2.7 U1.J4-15 | length 52.5
  L 01 (Top) w0.15: v1(50.75,47.275) U1.J4-15@50.75,48.35
  L 04 (Bot) w0.15: J2.7@10.51,65.48 10.51,63.53 15.065,58.975 38.525,58.975 43.325,54.175 47.275,54.175 48.625,52.825 48.625,48.55 49.9,47.275 v1(50.75,47.275)
B0_IO_C4: J2.8 U1.J4-21 | length 56.7
  L 01 (Top) w0.15: v1(51.775,46.925) 51.775,47.2 52.25,47.675 U1.J4-21@52.25,48.35
  L 04 (Bot) w0.15: J2.8@10.51,68.02 11.8,66.73 11.8,63.475 15.45,59.825 38.175,59.825 43.05,54.95 47.75,54.95 49.075,53.625 49.075,48.875 49.875,48.075 51.2,48.075 51.775,47.5 v1(51.775,46.925)
B0_IO_D13: J4.20 U1.J4-66 | length 33.3
  L 01 (Top) w0.15: U1.J4-66@63.25,53.65 63.25,57.2 65,58.95 80.65,58.95 85.55,63.85 85.55,66.86 J4.20@86.71,68.02
B0_IO_E13: J4.19 U1.J4-68 | length 30.8
  L 01 (Top) w0.15: U1.J4-68@63.75,53.65 63.75,57.1 65.175,58.525 81.275,58.525 86.71,63.96 J4.19@86.71,65.48
B0_IO_G9: J4.8 U1.J4-37 | length 32.8
  L 01 (Top) w0.15: U1.J4-37@56.25,48.35 56.25,49.375 v1(56.55,49.675)
  L 04 (Bot) w0.15: v1(56.55,49.675) 56.875,50 56.875,65.075 58.675,66.875 70.325,66.875 J4.8@71.47,68.02
B0_L01_N: J4.27 U1.J4-75 | length 41
  L 01 (Top) w0.15: U1.J4-75@65.75,48.35 65.75,47.775 65.83,47.695 65.83,47.214 66.334,46.71 78.741,46.71 96.165,64.134 96.165,65.46 96.185,65.48 J4.27@96.87,65.48
B0_L01_P: J4.28 U1.J4-77 | length 42.1
  L 01 (Top) w0.15: U1.J4-77@66.25,48.35 66.25,47.775 66.17,47.695 66.17,47.355 66.475,47.05 78.6,47.05 95.825,64.275 95.825,66.05 96.87,67.095 J4.28@96.87,68.02
B0_L03_N: J4.29 U1.J4-69 | length 46.3
  L 01 (Top) w0.15: U1.J4-69@64.25,48.35 64.25,47.775 64.33,47.695 64.33,46.439 64.835,45.934 64.934,45.835 65.159,45.61 79.666,45.61 98.715,64.659 98.715,65.48 98.715,65.625 99.265,65.625 J4.29@99.41,65.48
B0_L03_P: J4.30 U1.J4-71 | length 47.2
  L 01 (Top) w0.15: U1.J4-71@64.75,48.35 64.75,47.775 64.67,47.695 64.67,46.58 65.075,46.175 65.175,46.075 65.3,45.95 79.525,45.95 98.375,64.8 98.375,66.125 99.41,67.16 J4.30@99.41,68.02
B0_L04_N: J4.31 U1.J4-65 | length 51.1
  L 01 (Top) w0.15: U1.J4-65@63.25,48.35 63.25,47.775 63.33,47.695 63.33,45.514 64.459,44.385 80.791,44.385 101.201,64.795 101.25,64.844 101.25,65.48 101.25,65.5 101.27,65.48 J4.31@101.95,65.48
B0_L04_P: J4.32 U1.J4-67 | length 52.2
  L 01 (Top) w0.15: U1.J4-67@63.75,48.35 63.75,47.775 63.67,47.695 63.67,45.655 64.6,44.725 80.65,44.725 100.9,64.975 100.9,66.05 101.95,67.1 J4.32@101.95,68.02
B0_L05_N: J4.25 U1.J4-61 | length 40.9
  L 01 (Top) w0.15: U1.J4-61@62.25,48.35 62.25,48.925 62.17,49.005 62.17,49.77 62.85,50.45 66.3,50.45 71.725,55.875 85.35,55.875 85.7,56.225 90.175,60.7 90.275,60.8 93.625,64.15 93.625,65.45 93.655,65.48 J4.25@94.33,65.48
B0_L05_P: J4.26 U1.J4-59 | length 43.8
  L 01 (Top) w0.15: U1.J4-59@61.75,48.35 61.75,48.925 61.83,49.005 61.83,49.911 62.709,50.79 66.159,50.79 71.584,56.215 85.209,56.215 ; 85.46,56.465 85.209,56.215 ; 85.559,56.565 85.776,56.782 ; J4.26@94.33,68.02 94.33,67.08 93.285,66.035 93.285,64.291 90.034,61.04 89.935,60.941 85.776,56.782 ; 85.209,56.215 85.776,56.782
B0_L06_N: J4.17 U1.J4-62 | length 31.1
  L 01 (Top) w0.15: U1.J4-62@62.25,53.65 62.25,54.225 62.17,54.305 62.17,59.42 63.425,60.675 63.525,60.775 63.65,60.9 70.856,60.9 72.391,62.435 72.49,62.534 72.666,62.71 82.091,62.71 83.465,64.084 83.465,65.415 83.53,65.48 J4.17@84.17,65.48
B0_L06_P: J4.18 U1.J4-60 | length 33.4
  L 01 (Top) w0.15: U1.J4-60@61.75,53.65 61.75,54.225 61.83,54.305 61.83,59.561 63.185,60.916 63.284,61.015 63.509,61.24 70.715,61.24 72.15,62.675 72.25,62.775 72.525,63.05 81.95,63.05 83.125,64.225 83.125,66.05 84.17,67.095 J4.18@84.17,68.02
B0_L08_N: J4.21 U1.J4-57 | length 39.2
  L 01 (Top) w0.15: U1.J4-57@61.25,48.35 61.25,48.925 61.17,49.005 61.17,50.67 62.025,51.525 66.175,51.525 67.625,52.975 67.725,53.075 67.925,53.275 67.925,55.95 69.325,57.35 82.35,57.35 87.425,62.425 87.525,62.525 88.55,63.55 88.55,65.45 88.58,65.48 J4.21@89.25,65.48
B0_L08_P: J4.22 U1.J4-55 | length 41.5
  L 01 (Top) w0.15: U1.J4-55@60.75,48.35 60.75,48.925 60.83,49.005 60.83,50.811 61.884,51.865 66.034,51.865 67.385,53.216 67.484,53.315 67.585,53.416 67.585,56.091 69.184,57.69 82.209,57.69 87.185,62.666 87.284,62.765 88.21,63.691 88.21,66.06 89.25,67.1 J4.22@89.25,68.02
B0_L09_N: J4.4 U1.J4-48 | length 19.1
  L 01 (Top) w0.15: U1.J4-48@58.75,53.65 58.75,54.225 58.83,54.305 58.83,61.011 61.385,63.566 61.484,63.665 61.859,64.04 64.53,64.04 65.31,64.82 65.31,66.085 66.39,67.165 J4.4@66.39,68.02
B0_L09_P: J4.3 U1.J4-50 | length 16.8
  L 01 (Top) w0.15: U1.J4-50@59.25,53.65 59.25,54.225 59.17,54.305 59.17,60.87 61.625,63.325 61.725,63.425 62,63.7 64.67,63.7 65.65,64.68 65.65,65.425 65.705,65.48 J4.3@66.35,65.48
B0_L15_N: J4.11 U1.J4-51 | length 29.4
  L 01 (Top) w0.15: U1.J4-51@59.75,48.35 59.75,48.925 59.67,49.005 59.67,50.825 v1(59.95,50.825)
  L 04 (Bot) w0.15: v1(59.95,50.825) 59.67,50.825 59.67,51.905 59.325,52.25 59.3,52.275 59.3,54.525 60.525,55.75 60.625,55.85 67.15,62.375 73.95,62.375 75.85,64.275 75.85,65.48 75.85,65.5 76.53,65.5 J4.11@76.55,65.48
B0_L15_P: J4.12 U1.J4-49 | length 31.7
  L 01 (Top) w0.15: v1(59.05,50.825) 59.33,50.825 59.33,49.005 59.25,48.925 U1.J4-49@59.25,48.35
  L 04 (Bot) w0.15: v1(59.05,50.825) 59.33,50.825 59.33,51.764 59.084,52.01 59.06,52.035 58.96,52.134 58.96,54.666 60.285,55.991 60.384,56.09 67.009,62.715 73.809,62.715 75.51,64.416 75.51,65.96 76.55,67 J4.12@76.55,68.02
B0_L17_N: J2.35 U1.J4-30 | length 17.9
  L 01 (Top) w0.15: J2.35@46.07,65.48 46.74,65.48 46.76,65.46 46.76,64.084 46.86,63.985 46.934,63.91 48.034,62.81 51.784,62.81 54.33,60.264 54.33,54.305 54.25,54.225 U1.J4-30@54.25,53.65
B0_L17_P: J2.36 U1.J4-32 | length 20.2
  L 01 (Top) w0.15: J2.36@46.07,68.02 46.07,67.005 47.1,65.975 47.1,64.225 47.175,64.15 48.175,63.15 51.925,63.15 54.67,60.405 54.67,54.305 54.75,54.225 U1.J4-32@54.75,53.65
B0_L18_N: J2.31 U1.J4-26 | length 21.4
  L 01 (Top) w0.15: J2.31@40.99,65.48 41.615,65.48 41.685,65.41 41.685,64.434 42.709,63.41 45.909,63.41 47.509,61.81 51.259,61.81 53.33,59.739 53.33,54.305 53.25,54.225 U1.J4-26@53.25,53.65
B0_L18_P: J2.32 U1.J4-28 | length 23.7
  L 01 (Top) w0.15: J2.32@40.99,68.02 40.99,67.085 42.025,66.05 42.025,64.575 42.85,63.75 46.05,63.75 47.65,62.15 51.4,62.15 53.67,59.88 53.67,54.305 53.75,54.225 U1.J4-28@53.75,53.65
B0_L19_N: J2.28 U1.J4-18 | length 25.4
  L 01 (Top) w0.15: J2.28@35.91,68.02 35.91,67.04 36.95,66 36.95,63.575 41.85,58.675 49.825,58.675 51.17,57.33 51.17,54.305 51.25,54.225 U1.J4-18@51.25,53.65
B0_L19_P: J2.27 U1.J4-16 | length 23.1
  L 01 (Top) w0.15: J2.27@35.91,65.48 36.595,65.48 36.61,65.465 36.61,63.434 41.709,58.335 49.684,58.335 50.83,57.189 50.83,54.305 50.75,54.225 U1.J4-16@50.75,53.65
B0_L20_N: J2.14 U1.J4-31 | length 54.7
  L 01 (Top) w0.15: U1.J4-31@54.75,48.35 54.75,47.775 54.67,47.695 54.67,46.675 v1(54.95,46.675)
  L 04 (Bot) w0.15: J2.14@18.13,68.02 18.13,66.985 19.165,65.95 19.165,64.8 19.965,64 40.125,64 43.325,60.8 43.425,60.7 45.525,58.6 52.55,58.6 53.8,57.35 53.8,51.6 53.825,51.575 53.925,51.475 54.67,50.73 54.67,46.675 v1(54.95,46.675)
